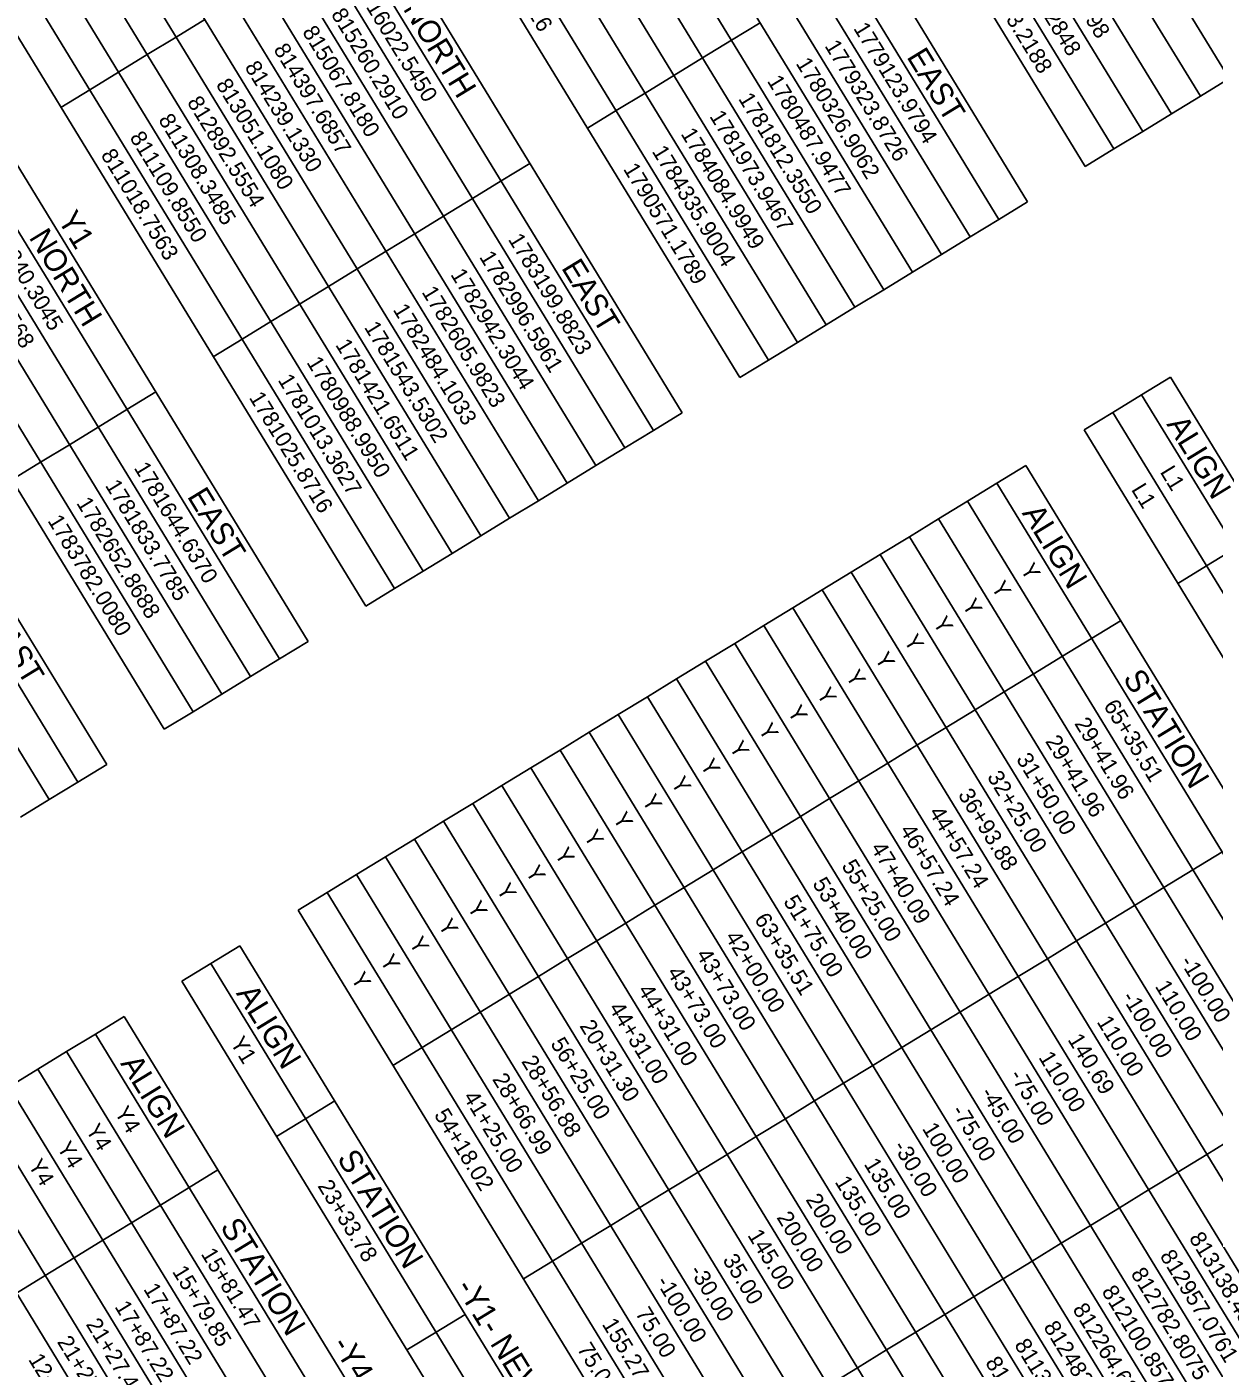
# Model space of a CAD drawing. Extents: x 1753086 to 1770987, y 792577 to 812636.
# Drawn here: x 1759624 to 1762877, y 804785 to 808460 of the extents above; entities that cross this region are included whole.
import ezdxf

# ---------------------------------------------------------------- set-up
doc = ezdxf.new("R2010")
doc.units = 0
for name, color, linetype in [('CTL Sheet Notes CELL', 7, 'Continuous'), ('CTL Sheet Table Cell', 7, 'Continuous'), ('CTL Sheet Text', 7, 'Continuous')]:
    doc.layers.add(name, color=color, linetype=linetype)

msp = doc.modelspace()

# ---------------------------------------------------------------- linework, layer by layer
at = {"layer": 'CTL Sheet Table Cell'}
for p, q in [((1761569, 810525.3), (1762917.9, 808317.6)), ((1761490.2, 810477.2), (1762839.1, 808269.4)), ((1761411.3, 810429), (1762760.2, 808221.3)), ((1761332.5, 810380.8), (1762681.4, 808173.1)), ((1761253.6, 810332.6), (1762602.5, 808124.9)), ((1761174.8, 810284.5), (1762523.7, 808076.7)), ((1761017.1, 810188.1), (1762366, 807980.4)), ((1760938.2, 810139.9), (1762287.2, 807932.2)), ((1760859.4, 810091.8), (1762208.3, 807884)), ((1760780.5, 810043.6), (1762129.5, 807835.9)), ((1760701.7, 809995.4), (1762050.6, 807787.7)), ((1760622.9, 809947.2), (1761971.8, 807739.5)), ((1760544, 809899.1), (1761892.9, 807691.3)), ((1760465.2, 809850.9), (1761814.1, 807643.2)), ((1760386.3, 809802.7), (1761735.2, 807595)), ((1760307.5, 809754.5), (1761656.4, 807546.8)), ((1760228.6, 809706.4), (1761577.5, 807498.6)), ((1760070.9, 809610), (1761419.8, 807402.3)), ((1759992.1, 809561.8), (1761341, 807354.1)), ((1759913.2, 809513.7), (1761262.1, 807305.9)), ((1759834.4, 809465.5), (1761183.3, 807257.8)), ((1759755.5, 809417.3), (1761104.5, 807209.6)), ((1759676.7, 809369.1), (1761025.6, 807161.4)), ((1759597.8, 809321), (1760946.8, 807113.2)), ((1759519, 809272.8), (1760867.9, 807065.1)), ((1759440.1, 809224.6), (1760789.1, 807016.9)), ((1759361.3, 809176.4), (1760710.2, 806968.7)), ((1759282.5, 809128.3), (1760631.4, 806920.5)), ((1759203.6, 809080.1), (1760552.5, 806872.4)), ((1759045.9, 808983.7), (1760394.8, 806776)), ((1758967.1, 808935.5), (1760316, 806727.8)), ((1758888.2, 808887.4), (1760237.1, 806679.7)), ((1758809.4, 808839.2), (1760158.3, 806631.5)), ((1758730.5, 808791), (1760079.4, 806583.3)), ((1758651.7, 808742.8), (1760000.6, 806535.1)), ((1758494, 808646.5), (1759842.9, 806438.8)), ((1758415.1, 808598.3), (1759764.1, 806390.6)), ((1758336.3, 808550.1), (1759685.2, 806342.4)), ((1760111.7, 808479.9), (1760032.9, 808431.7)), ((1761633.1, 808471), (1761554.2, 808422.9)), ((1760032.9, 808431.7), (1759954, 808383.6)), ((1761554.2, 808422.9), (1761475.4, 808374.7)), ((1759954, 808383.6), (1759875.2, 808335.4)), ((1761475.4, 808374.7), (1761396.6, 808326.5)), ((1759875.2, 808335.4), (1759796.3, 808287.2)), ((1761396.6, 808326.5), (1761317.7, 808278.3)), ((1759796.3, 808287.2), (1759717.5, 808239)), ((1762917.9, 808317.6), (1762839.1, 808269.4)), ((1761317.7, 808278.3), (1761238.9, 808230.2)), ((1762839.1, 808269.4), (1762760.2, 808221.3)), ((1761238.9, 808230.2), (1761160, 808182)), ((1762760.2, 808221.3), (1762681.4, 808173.1)), ((1762681.4, 808173.1), (1762602.5, 808124.9)), ((1762602.5, 808124.9), (1762523.7, 808076.7)), ((1761002.3, 808085.6), (1760923.5, 808037.5)), ((1760923.5, 808037.5), (1760844.6, 807989.3)), ((1760844.6, 807989.3), (1760765.8, 807941.1)), ((1762366, 807980.4), (1762287.2, 807932.2)), ((1760765.8, 807941.1), (1760686.9, 807892.9)), ((1762287.2, 807932.2), (1762208.3, 807884)), ((1760686.9, 807892.9), (1760608.1, 807844.8)), ((1762208.3, 807884), (1762129.5, 807835.9)), ((1760608.1, 807844.8), (1760529.2, 807796.6)), ((1762129.5, 807835.9), (1762050.6, 807787.7)), ((1760529.2, 807796.6), (1760450.4, 807748.4)), ((1762050.6, 807787.7), (1761971.8, 807739.5)), ((1760450.4, 807748.4), (1760371.5, 807700.2)), ((1761971.8, 807739.5), (1761892.9, 807691.3)), ((1760371.5, 807700.2), (1760292.7, 807652)), ((1761892.9, 807691.3), (1761814.1, 807643.2)), ((1760292.7, 807652), (1760213.8, 807603.9)), ((1761814.1, 807643.2), (1761735.2, 807595)), ((1760213.8, 807603.9), (1760135, 807555.7)), ((1761735.2, 807595), (1761656.4, 807546.8)), ((1761656.4, 807546.8), (1761577.5, 807498.6)), ((1762756.9, 807499.7), (1762678.1, 807451.5)), ((1762756.9, 807499.7), (1764555.5, 804556.1)), ((1759977.3, 807459.3), (1759898.5, 807411.2)), ((1762678.1, 807451.5), (1762599.2, 807403.3)), ((1762678.1, 807451.5), (1764476.6, 804507.9)), ((1759898.5, 807411.2), (1759819.6, 807363)), ((1761419.8, 807402.3), (1761341, 807354.1)), ((1762599.2, 807403.3), (1762520.4, 807355.2)), ((1762599.2, 807403.3), (1764397.8, 804459.7)), ((1759819.6, 807363), (1759740.8, 807314.8)), ((1761341, 807354.1), (1761262.1, 807305.9)), ((1762520.4, 807355.2), (1764318.9, 804411.5)), ((1759740.8, 807314.8), (1759661.9, 807266.6)), ((1761262.1, 807305.9), (1761183.3, 807257.8)), ((1759661.9, 807266.6), (1759583.1, 807218.5)), ((1761183.3, 807257.8), (1761104.5, 807209.6)), ((1762360.9, 807257.7), (1762281.2, 807209)), ((1762360.9, 807257.7), (1764179.9, 804280.6)), ((1761104.5, 807209.6), (1761025.6, 807161.4)), ((1762281.2, 807209), (1762201.4, 807160.3)), ((1762281.2, 807209), (1764100.2, 804231.9)), ((1761025.6, 807161.4), (1760946.8, 807113.2)), ((1762201.4, 807160.3), (1762121.7, 807111.5)), ((1762201.4, 807160.3), (1764020.4, 804183.2)), ((1760946.8, 807113.2), (1760867.9, 807065.1)), ((1762121.7, 807111.5), (1762041.9, 807062.8)), ((1762121.7, 807111.5), (1763940.7, 804134.5)), ((1760867.9, 807065.1), (1760789.1, 807016.9)), ((1762041.9, 807062.8), (1761962.2, 807014.1)), ((1762041.9, 807062.8), (1763860.9, 804085.7)), ((1760789.1, 807016.9), (1760710.2, 806968.7)), ((1761962.2, 807014.1), (1761882.4, 806965.4)), ((1761962.2, 807014.1), (1763781.2, 804037)), ((1762935, 807031), (1762856.2, 806982.8)), ((1760710.2, 806968.7), (1760631.4, 806920.5)), ((1761882.4, 806965.4), (1761802.7, 806916.7)), ((1761882.4, 806965.4), (1763701.4, 803988.3)), ((1762856.2, 806982.8), (1762777.3, 806934.6)), ((1760631.4, 806920.5), (1760552.5, 806872.4)), ((1761802.7, 806916.7), (1761723, 806867.9)), ((1761802.7, 806916.7), (1763621.7, 803939.6)), ((1761723, 806867.9), (1761643.2, 806819.2)), ((1761723, 806867.9), (1763542, 803890.9)), ((1761643.2, 806819.2), (1761563.5, 806770.5)), ((1761643.2, 806819.2), (1763462.2, 803842.1)), ((1762620.8, 806832.4), (1762541, 806783.7)), ((1760394.8, 806776), (1760316, 806727.8)), ((1762541, 806783.7), (1762461.3, 806735)), ((1761563.5, 806770.5), (1761483.7, 806721.8)), ((1761563.5, 806770.5), (1763382.5, 803793.4)), ((1760316, 806727.8), (1760237.1, 806679.7)), ((1761483.7, 806721.8), (1761404, 806673)), ((1761483.7, 806721.8), (1763302.7, 803744.7)), ((1762461.3, 806735), (1762381.5, 806686.2)), ((1760237.1, 806679.7), (1760158.3, 806631.5)), ((1761404, 806673), (1761324.2, 806624.3)), ((1761404, 806673), (1763223, 803696)), ((1762381.5, 806686.2), (1762301.8, 806637.5)), ((1760158.3, 806631.5), (1760079.4, 806583.3)), ((1762301.8, 806637.5), (1762222, 806588.8)), ((1761324.2, 806624.3), (1761244.5, 806575.6)), ((1761324.2, 806624.3), (1763143.2, 803647.2)), ((1760079.4, 806583.3), (1760000.6, 806535.1)), ((1761244.5, 806575.6), (1761164.8, 806526.9)), ((1761244.5, 806575.6), (1763063.5, 803598.5)), ((1762222, 806588.8), (1762142.3, 806540.1)), ((1761164.8, 806526.9), (1761085, 806478.1)), ((1761164.8, 806526.9), (1762983.7, 803549.8)), ((1762142.3, 806540.1), (1762062.6, 806491.4)), ((1762062.6, 806491.4), (1761982.8, 806442.6)), ((1761085, 806478.1), (1761005.3, 806429.4)), ((1761085, 806478.1), (1762904, 803501.1)), ((1759842.9, 806438.8), (1759764.1, 806390.6)), ((1761005.3, 806429.4), (1760925.5, 806380.7)), ((1761005.3, 806429.4), (1762824.3, 803452.3)), ((1761982.8, 806442.6), (1761903.1, 806393.9)), ((1759764.1, 806390.6), (1759685.2, 806342.4)), ((1760925.5, 806380.7), (1760845.8, 806332)), ((1760925.5, 806380.7), (1762744.5, 803403.6)), ((1761903.1, 806393.9), (1761823.3, 806345.2)), ((1759685.2, 806342.4), (1759606.4, 806294.2)), ((1761823.3, 806345.2), (1761743.6, 806296.5)), ((1760845.8, 806332), (1760766, 806283.3)), ((1760845.8, 806332), (1762664.8, 803354.9)), ((1760766, 806283.3), (1760686.3, 806234.5)), ((1760766, 806283.3), (1762585, 803306.2)), ((1761743.6, 806296.5), (1761663.8, 806247.7)), ((1760686.3, 806234.5), (1760606.6, 806185.8)), ((1760686.3, 806234.5), (1762505.3, 803257.5)), ((1761663.8, 806247.7), (1761584.1, 806199)), ((1761584.1, 806199), (1761504.4, 806150.3)), ((1762898.3, 806198.9), (1762818.6, 806150.2)), ((1760606.6, 806185.8), (1760526.8, 806137.1)), ((1760606.6, 806185.8), (1762425.5, 803208.7)), ((1761504.4, 806150.3), (1761424.6, 806101.6)), ((1762818.6, 806150.2), (1762738.8, 806101.5)), ((1760526.8, 806137.1), (1760447.1, 806088.4)), ((1760526.8, 806137.1), (1762345.8, 803160)), ((1760447.1, 806088.4), (1760367.3, 806039.6)), ((1760447.1, 806088.4), (1762266.1, 803111.3)), ((1761424.6, 806101.6), (1761344.9, 806052.8)), ((1762738.8, 806101.5), (1762659.1, 806052.7)), ((1761344.9, 806052.8), (1761265.1, 806004.1)), ((1762659.1, 806052.7), (1762579.3, 806004)), ((1760367.3, 806039.6), (1762186.3, 803062.6)), ((1761265.1, 806004.1), (1761185.4, 805955.4)), ((1762579.3, 806004), (1762499.6, 805955.3)), ((1760207.8, 805942.2), (1760128.1, 805893.5)), ((1760207.8, 805942.2), (1762026.8, 802965.1)), ((1761185.4, 805955.4), (1761105.6, 805906.7)), ((1762499.6, 805955.3), (1762419.9, 805906.6)), ((1760128.1, 805893.5), (1760048.4, 805844.7)), ((1760128.1, 805893.5), (1761947.1, 802916.4)), ((1761105.6, 805906.7), (1761025.9, 805858)), ((1762419.9, 805906.6), (1762340.1, 805857.9)), ((1761025.9, 805858), (1760946.2, 805809.2)), ((1762340.1, 805857.9), (1762260.4, 805809.1)), ((1760048.4, 805844.7), (1761867.3, 802867.7)), ((1760946.2, 805809.2), (1760866.4, 805760.5)), ((1762260.4, 805809.1), (1762180.6, 805760.4)), ((1759890.7, 805748.4), (1759811.8, 805700.2)), ((1759890.7, 805748.4), (1761689.2, 802804.8)), ((1760866.4, 805760.5), (1760786.7, 805711.8)), ((1762180.6, 805760.4), (1762100.9, 805711.7)), ((1760786.7, 805711.8), (1760706.9, 805663.1)), ((1762100.9, 805711.7), (1762021.1, 805663)), ((1759811.8, 805700.2), (1759733, 805652)), ((1759811.8, 805700.2), (1761610.4, 802756.6)), ((1759733, 805652), (1759654.1, 805603.9)), ((1759733, 805652), (1761531.5, 802708.4)), ((1760706.9, 805663.1), (1760627.2, 805614.3)), ((1762021.1, 805663), (1761941.4, 805614.2)), ((1759654.1, 805603.9), (1759575.3, 805555.7)), ((1759654.1, 805603.9), (1761452.7, 802660.2)), ((1761941.4, 805614.2), (1761861.7, 805565.5)), ((1761861.7, 805565.5), (1761781.9, 805516.8)), ((1759575.3, 805555.7), (1761373.8, 802612.1)), ((1759496.4, 805507.5), (1761295, 802563.9)), ((1760467.7, 805516.9), (1760387.9, 805468.2)), ((1761781.9, 805516.8), (1761702.2, 805468.1)), ((1759417.6, 805459.3), (1761216.1, 802515.7)), ((1760387.9, 805468.2), (1760308.2, 805419.4)), ((1761702.2, 805468.1), (1761622.4, 805419.3)), ((1761622.4, 805419.3), (1761542.7, 805370.6)), ((1762936.6, 805419.2), (1762856.9, 805370.5)), ((1759338.7, 805411.2), (1761137.3, 802467.5)), ((1761542.7, 805370.6), (1761462.9, 805321.9)), ((1762856.9, 805370.5), (1762777.2, 805321.8)), ((1760147.6, 805327.9), (1760068.7, 805279.7)), ((1761462.9, 805321.9), (1761383.2, 805273.2)), ((1762777.2, 805321.8), (1762697.4, 805273.1)), ((1760068.7, 805279.7), (1759989.9, 805231.5)), ((1761383.2, 805273.2), (1761303.5, 805224.5)), ((1762697.4, 805273.1), (1762617.7, 805224.3)), ((1759989.9, 805231.5), (1759911.1, 805183.3)), ((1761303.5, 805224.5), (1761223.7, 805175.7)), ((1762617.7, 805224.3), (1762537.9, 805175.6)), ((1759911.1, 805183.3), (1759832.2, 805135.2)), ((1761223.7, 805175.7), (1761144, 805127)), ((1762537.9, 805175.6), (1762458.2, 805126.9)), ((1759832.2, 805135.2), (1759753.4, 805087)), ((1761144, 805127), (1761064.2, 805078.3)), ((1762458.2, 805126.9), (1762378.4, 805078.2)), ((1759753.4, 805087), (1759674.5, 805038.8)), ((1761064.2, 805078.3), (1760984.5, 805029.6)), ((1762378.4, 805078.2), (1762298.7, 805029.5)), ((1759674.5, 805038.8), (1759595.7, 804990.6)), ((1762298.7, 805029.5), (1762219, 804980.7)), ((1762219, 804980.7), (1762139.2, 804932)), ((1760825, 804932.1), (1760745.3, 804883.4)), ((1762139.2, 804932), (1762059.5, 804883.3)), ((1760745.3, 804883.4), (1760665.5, 804834.7)), ((1762059.5, 804883.3), (1761979.7, 804834.6)), ((1761979.7, 804834.6), (1761900, 804785.8)), ((1761900, 804785.8), (1761820.2, 804737.1))]:
    msp.add_line(p, q, dxfattribs=at)

# ---------------------------------------------------------------- texts
at = {"layer": 'CTL Sheet Notes CELL'}
for s, height, p in [('NORTH', 61.6, (1760653.5, 808508.8)), ('EAST', 61.6, (1762033.1, 808377.5)), ('Y1', 61.6, (1759707, 807931.4)), ('NORTH', 61.6, (1759628.5, 807882.6)), ('EAST', 61.6, (1761087, 807799.4)), ('ALIGN', 61.6, (1762745.3, 807371)), ('EAST', 61.6, (1760061.9, 807173.1)), ('ALIGN', 62.3, (1762349.2, 807127.5)), ('EAST', 61.6, (1759510, 806835.9)), ('STATION', 62.3, (1762625.5, 806675.2)), ('ALIGN', 62.3, (1760196.1, 805812)), ('ALIGN', 61.6, (1759879.1, 805619.7)), ('STATION', 62.3, (1760472.5, 805359.7)), ('STATION', 61.6, (1760152.3, 805172.5)), ('-Y1- NEW R/W MONUMENT', 62.3, (1760797.6, 805006.8)), ('-Y4- NEW R/W MONUMENTS', 61.6, (1760457.9, 804849.6))]:
    msp.add_text(s, height=height, rotation=301.4249, dxfattribs=at).set_placement(p)
at = {"layer": 'CTL Sheet Text'}
for s, height, p in [('807090.9816', 44, (1760850.5, 808734.9)), ('1783631.1698', 44, (1762360.5, 808744.7)), ('1783883.2848', 44, (1762281.7, 808696.5)), ('1790243.2188', 44, (1762202.8, 808648.3)), ('816022.5450', 44, (1760535.1, 808542.2)), ('815260.2910', 44, (1760456.3, 808494.1)), ('1779123.9794', 44, (1761887.4, 808455.6)), ('815067.8180', 44, (1760377.4, 808445.9)), ('814397.6857', 44, (1760298.6, 808397.7)), ('1779323.8726', 44, (1761808.6, 808407.5)), ('814239.1330', 44, (1760219.7, 808349.5)), ('1780326.9062', 44, (1761729.7, 808359.3)), ('813051.1080', 44, (1760140.9, 808301.4)), ('1780487.9477', 44, (1761650.9, 808311.1)), ('812892.5554', 44, (1760062, 808253.2)), ('1781812.3550', 44, (1761572, 808262.9)), ('811308.3485', 44, (1759983.2, 808205)), ('1781973.9467', 44, (1761493.2, 808214.7)), ('811109.8550', 44, (1759904.4, 808156.8)), ('1784084.9949', 44, (1761414.4, 808166.6)), ('811018.7563', 44, (1759825.5, 808108.7)), ('1784335.9004', 44, (1761335.5, 808118.4)), ('1790571.1789', 44, (1761256.7, 808070.2)), ('815340.3045', 44, (1759510.1, 807916)), ('815068.1568', 44, (1759431.3, 807867.8)), ('1783199.8823', 44, (1760941.3, 807877.5)), ('1782996.5961', 44, (1760862.4, 807829.3)), ('1782942.3044', 44, (1760783.6, 807781.2)), ('1782605.9823', 44, (1760704.7, 807733)), ('1782484.1033', 44, (1760625.9, 807684.8)), ('1781543.5302', 44, (1760547, 807636.6)), ('1781421.6511', 44, (1760468.2, 807588.5)), ('1780988.9950', 44, (1760389.3, 807540.3)), ('1781013.3627', 44, (1760310.5, 807492.1)), ('1781025.8716', 44, (1760231.6, 807443.9)), ('1781644.6370', 44, (1759916.3, 807251.2)), ('L1', 44, (1762727.4, 807240)), ('1781833.7785', 44, (1759837.4, 807203.1)), ('L1', 44, (1762648.6, 807191.8)), ('1782652.8688', 44, (1759758.6, 807154.9)), ('1783782.0080', 44, (1759679.7, 807106.7)), ('Y', 44.5, (1762344.6, 806972.9)), ('Y', 44.5, (1762264.8, 806924.2)), ('Y', 44.5, (1762185.1, 806875.5)), ('Y', 44.5, (1762105.3, 806826.8)), ('Y', 44.5, (1762025.6, 806778)), ('Y', 44.5, (1761945.8, 806729.3)), ('Y', 44.5, (1761866.1, 806680.6)), ('Y', 44.5, (1761786.4, 806631.9)), ('Y', 44.5, (1761706.6, 806583.2)), ('65+35.51', 44.5, (1762572.6, 806599.8)), ('Y', 44.5, (1761626.9, 806534.4)), ('29+41.96', 44.5, (1762492.8, 806551)), ('29+41.96', 44.5, (1762413.1, 806502.3)), ('Y', 44.5, (1761547.1, 806485.7)), ('Y', 44.5, (1761467.4, 806437)), ('31+50.00', 44.5, (1762333.3, 806453.6)), ('Y', 44.5, (1761387.6, 806388.3)), ('32+25.00', 44.5, (1762253.6, 806404.9)), ('36+93.88', 44.5, (1762173.9, 806356.1)), ('Y', 44.5, (1761307.9, 806339.5)), ('Y', 44.5, (1761228.2, 806290.8)), ('44+57.24', 44.5, (1762094.1, 806307.4)), ('Y', 44.5, (1761148.4, 806242.1)), ('46+57.24', 44.5, (1762014.4, 806258.7)), ('Y', 44.5, (1761068.7, 806193.4)), ('47+40.09', 44.5, (1761934.6, 806210)), ('Y', 44.5, (1760988.9, 806144.6)), ('55+25.00', 44.5, (1761854.9, 806161.2)), ('Y', 44.5, (1760909.2, 806095.9)), ('53+40.00', 44.5, (1761775.1, 806112.5)), ('51+75.00', 44.5, (1761695.4, 806063.8)), ('Y', 44.5, (1760829.4, 806047.2)), ('Y', 44.5, (1760749.7, 805998.5)), ('63+35.51', 44.5, (1761615.7, 806015.1)), ('Y', 44.5, (1760669.9, 805949.8)), ('42+00.00', 44.5, (1761535.9, 805966.4)), ('Y', 44.5, (1760590.2, 805901)), ('43+73.00', 44.5, (1761456.2, 805917.6)), ('-100.00', 44.5, (1762781.9, 805898.7)), ('Y', 44.5, (1760510.5, 805852.3)), ('43+73.00', 44.5, (1761376.4, 805868.9)), ('44+31.00', 44.5, (1761296.7, 805820.2)), ('110.00', 44.5, (1762713.7, 805831.1)), ('-100.00', 44.5, (1762622.4, 805801.2)), ('44+31.00', 44.5, (1761216.9, 805771.5)), ('110.00', 44.5, (1762554.2, 805733.7)), ('20+31.30', 44.5, (1761137.2, 805722.7)), ('Y1', 44.5, (1760180, 805676.3)), ('56+25.00', 44.5, (1761057.4, 805674)), ('140.69', 44.5, (1762474.4, 805685)), ('28+56.88', 44.5, (1760977.7, 805625.3)), ('110.00', 44.5, (1762394.7, 805636.2)), ('28+66.99', 44.5, (1760898, 805576.6)), ('-75.00', 44.5, (1762314.9, 805587.5)), ('41+25.00', 44.5, (1760818.2, 805527.8)), ('-45.00', 44.5, (1762235.2, 805538.8)), ('Y4', 44, (1759863.1, 805485.4)), ('54+18.02', 44.5, (1760738.5, 805479.1)), ('-75.00', 44.5, (1762155.5, 805490.1)), ('Y4', 44, (1759784.3, 805437.3)), ('100.00', 44.5, (1762075.7, 805441.3)), ('Y4', 44, (1759705.4, 805389.1)), ('-30.00', 44.5, (1761996, 805392.6)), ('Y4', 44, (1759626.6, 805340.9)), ('135.00', 44.5, (1761916.2, 805343.9)), ('135.00', 44.5, (1761836.5, 805295.2)), ('23+33.78', 44.5, (1760419.5, 805284.2)), ('200.00', 44.5, (1761756.7, 805246.5)), ('200.00', 44.5, (1761677, 805197.7)), ('145.00', 44.5, (1761597.3, 805149)), ('813138.4394', 44.5, (1762806.7, 805141.2)), ('15+81.47', 44, (1760099.9, 805097.8)), ('35.00', 44.5, (1761529, 805081.4)), ('812957.0761', 44.5, (1762726.9, 805092.5)), ('15+79.85', 44, (1760021.1, 805049.7)), ('-30.00', 44.5, (1761437.8, 805051.6)), ('812782.8075', 44.5, (1762647.2, 805043.8)), ('17+87.22', 44, (1759942.3, 805001.5)), ('-100.00', 44.5, (1761346.5, 805021.7)), ('812100.8571', 44.5, (1762567.4, 804995)), ('17+87.22', 44, (1759863.4, 804953.3)), ('75.00', 44.5, (1761289.8, 804935.3)), ('812264.6260', 44.5, (1762487.7, 804946.3)), ('21+27.41', 44, (1759784.6, 804905.1)), ('155.27', 44.5, (1761198.5, 804905.4)), ('812482.4060', 44.5, (1762408, 804897.6)), ('21+27.42', 44, (1759705.7, 804857)), ('811311.1506', 44.5, (1762328.2, 804848.9)), ('75.00', 44.5, (1761130.3, 804837.8)), ('12+00.00', 44, (1759626.9, 804808.8)), ('813336.5933', 44.5, (1762248.5, 804800.1))]:
    msp.add_text(s, height=height, rotation=301.4249, dxfattribs=at).set_placement(p)

doc.saveas('drawing.dxf')
